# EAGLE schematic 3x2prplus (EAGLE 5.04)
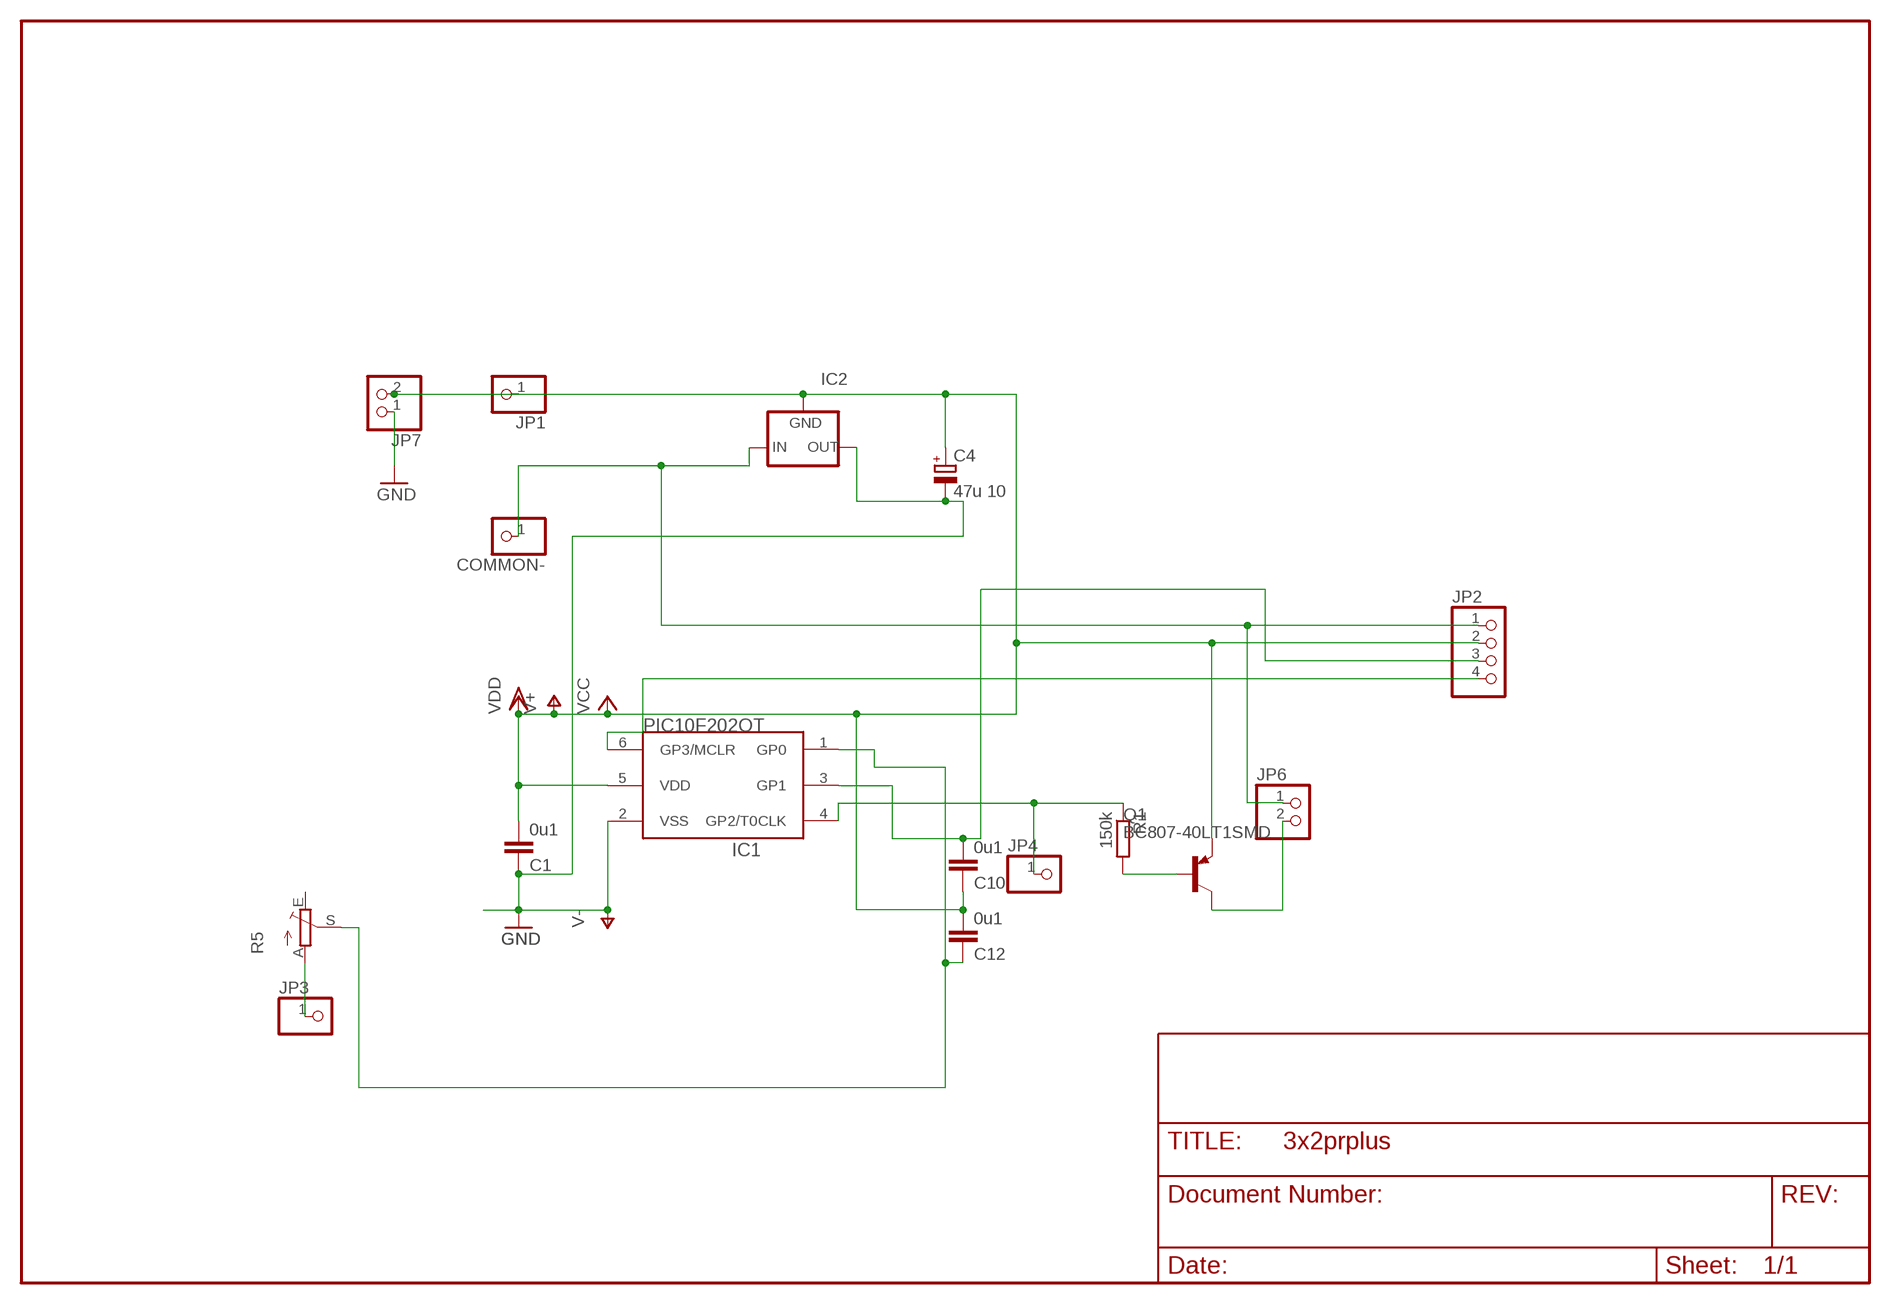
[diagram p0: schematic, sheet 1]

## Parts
C1  0u1  C-EUC1206  [C1206]
C4  47u 10  CPOL-EUE2.5-6  [E2,5-6]
C10  0u1  C-EUC0805  [C0805]
C12  0u1  C-EUC0805  [C0805]
COMMON-  PINHD-1X1  [1X01]
IC1  PIC10F202OT  [SOT23-6]
IC2  79LXX  [79LXX]
JP1  PINHD-1X1  [1X01]
JP2  PINHD-1X4  [1X04]
JP3  PINHD-1X1  [1X01]
JP4  PINHD-1X1  [1X01]
JP6  PINHD-1X2  [1X02]
JP7  PINHD-1X2  [1X02]
Q1  BC807-40LT1SMD  [SOT23-BEC]
R1  150k  R-EU_R0805  [R0805]
R5  TRIM_EU-CA6V  [CA6V]

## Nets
GND: C1.1 C4.- IC1.2(VSS) IC2.OUT JP7.1 ; supply symbol labelled V-
N$1: C10.2 IC1.3(GP1) JP2.3
N$2: Q1.B R1.2
N$3: IC1.6(GP3/MCLR) JP2.4
N$4: JP6.2 Q1.C
N$5: IC1.4(GP2/T0CLK) JP4.1 R1.1
N$8: COMMON-.1 IC2.IN JP2.1 JP6.1
N$9: JP3.1 R5.A
N$13: C12.1 IC1.1(GP0) R5.S
V+: C1.2 C4.+ C10.1 C12.2 IC1.5(VDD) IC2.GND JP1.1 JP2.2 JP7.2 Q1.E ; supply symbol labelled VCC, VDD
Unconnected: R5.E

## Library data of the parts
C1 C10 C12 = rcl:C-EU: CAPACITOR, European symbol
C4 = rcl:CPOL-EU: POLARIZED CAPACITOR, European symbol
COMMON- JP1 JP3 JP4 = pinhead:PINHD-1X1: PIN HEADER
IC1 = microchip-5:PIC10F20*: uPC nW 0,25/0,5k Program Flash memory
IC2 = v-reg:79LXX: VOLTAGE REGULATOR
JP2 = pinhead(2):PINHD-1X4: PIN HEADER
JP6 JP7 = pinhead:PINHD-1X2: PIN HEADER
Q1 = transistor-pnp:BC807*: PNP Transistror
R1 = rcl:R-EU_: RESISTOR, European symbol
R5 = pot:TRIM_EU-: POTENTIOMETER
